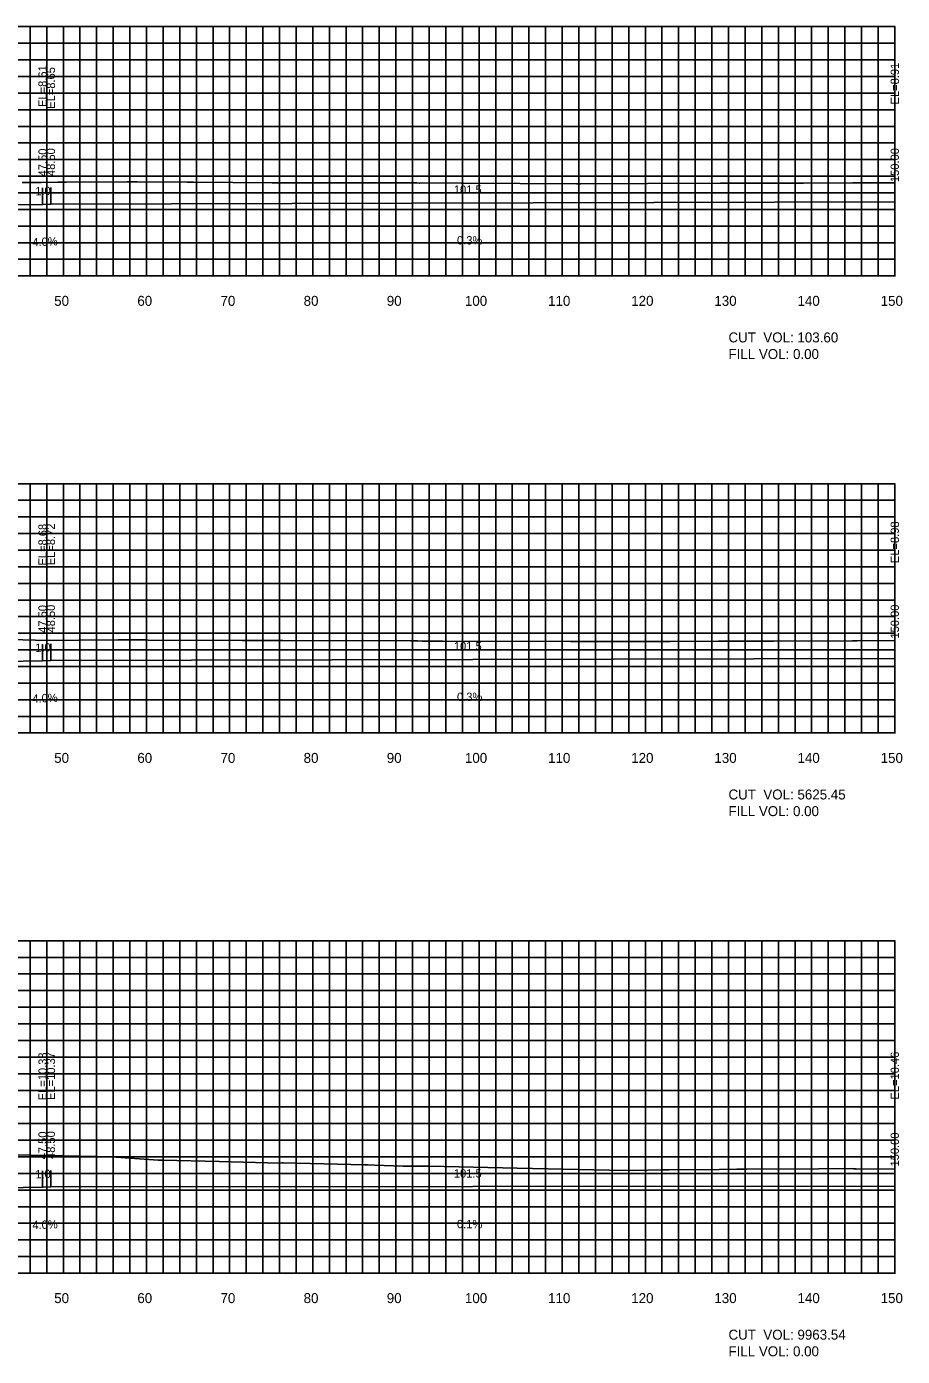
# Model space of a CAD drawing. Extents: x 1797789 to 1803805, y 249066 to 250293.
# Drawn here: x 1803356.6 to 1803461.9, y 250089.4 to 250249.4 of the extents above; entities that cross this region are included whole.
import ezdxf

# ---------------------------------------------------------------- set-up
doc = ezdxf.new("R2010")
doc.units = 0
for name, color, linetype in [('10', 7, 'Continuous'), ('3', 7, 'Continuous'), ('4', 7, 'Continuous'), ('60', 7, 'Continuous'), ('ANNO-TXT', 7, 'Continuous'), ('CL-CNST', 7, 'Continuous'), ('Level 62', 7, 'Continuous'), ('M-ROADS', 7, 'Continuous')]:
    doc.layers.add(name, color=color, linetype=linetype)

msp = doc.modelspace()

# ---------------------------------------------------------------- linework, layer by layer
for p, q in [((1803358.5, 250228.04), (1803358.5, 250230.04)), ((1803359.5, 250228.08), (1803359.5, 250230.08)), ((1803461, 250228.34), (1803461, 250230.34)), ((1803358.5, 250173.11), (1803358.5, 250175.11)), ((1803359.5, 250173.15), (1803359.5, 250175.15)), ((1803461, 250173.41), (1803461, 250175.41)), ((1803358.5, 250109.76), (1803358.5, 250111.76)), ((1803359.5, 250109.8), (1803359.5, 250111.8)), ((1803461, 250109.89), (1803461, 250111.89))]:
    msp.add_line(p, q)
at = {"layer": '60'}
for p, q in [((1803461, 250219.43), (1803461, 250249.43)), ((1803461.06, 250249.43), (1803461, 250249.43)), ((1803461.06, 250239.43), (1803461, 250239.43)), ((1803461.06, 250229.43), (1803461, 250229.43)), ((1803161, 250219.43), (1803461, 250219.43)), ((1803361, 250219.37), (1803361, 250219.43)), ((1803371, 250219.37), (1803371, 250219.43)), ((1803381, 250219.37), (1803381, 250219.43)), ((1803391, 250219.37), (1803391, 250219.43)), ((1803401, 250219.37), (1803401, 250219.43)), ((1803411, 250219.37), (1803411, 250219.43)), ((1803421, 250219.37), (1803421, 250219.43)), ((1803431, 250219.37), (1803431, 250219.43)), ((1803441, 250219.37), (1803441, 250219.43)), ((1803451, 250219.37), (1803451, 250219.43)), ((1803461, 250219.37), (1803461, 250219.43)), ((1803461.06, 250219.43), (1803461, 250219.43)), ((1803461, 250164.43), (1803461, 250194.43)), ((1803461.06, 250194.43), (1803461, 250194.43)), ((1803461.06, 250184.43), (1803461, 250184.43)), ((1803461.06, 250174.43), (1803461, 250174.43)), ((1803161, 250164.43), (1803461, 250164.43)), ((1803361, 250164.37), (1803361, 250164.43)), ((1803371, 250164.37), (1803371, 250164.43)), ((1803381, 250164.37), (1803381, 250164.43)), ((1803391, 250164.37), (1803391, 250164.43)), ((1803401, 250164.37), (1803401, 250164.43)), ((1803411, 250164.37), (1803411, 250164.43)), ((1803421, 250164.37), (1803421, 250164.43)), ((1803431, 250164.37), (1803431, 250164.43)), ((1803441, 250164.37), (1803441, 250164.43)), ((1803451, 250164.37), (1803451, 250164.43)), ((1803461, 250164.37), (1803461, 250164.43)), ((1803461.06, 250164.43), (1803461, 250164.43)), ((1803461, 250099.43), (1803461, 250139.43)), ((1803461.06, 250139.43), (1803461, 250139.43)), ((1803461.06, 250129.43), (1803461, 250129.43)), ((1803461.06, 250119.43), (1803461, 250119.43)), ((1803461.06, 250109.43), (1803461, 250109.43)), ((1803161, 250099.43), (1803461, 250099.43)), ((1803361, 250099.37), (1803361, 250099.43)), ((1803371, 250099.37), (1803371, 250099.43)), ((1803381, 250099.37), (1803381, 250099.43)), ((1803391, 250099.37), (1803391, 250099.43)), ((1803401, 250099.37), (1803401, 250099.43)), ((1803411, 250099.37), (1803411, 250099.43)), ((1803421, 250099.37), (1803421, 250099.43)), ((1803431, 250099.37), (1803431, 250099.43)), ((1803441, 250099.37), (1803441, 250099.43)), ((1803451, 250099.37), (1803451, 250099.43)), ((1803461, 250099.37), (1803461, 250099.43)), ((1803461.06, 250099.43), (1803461, 250099.43))]:
    msp.add_line(p, q, dxfattribs=at)
at = {"layer": 'CL-CNST'}
for points in [[(1803249.99, 250232.25), (1803262.5, 250228.08), (1803263.5, 250228.04), (1803270.5, 250227.93), (1803270.5, 250227.93), (1803270.83, 250227.93), (1803271, 250227.43), (1803273, 250227.59), (1803277, 250227.68), (1803311, 250228.43), (1803345, 250227.68), (1803349, 250227.59), (1803351, 250227.43), (1803351.17, 250227.93), (1803351.5, 250227.93), (1803351.5, 250227.93), (1803358.5, 250228.04), (1803359.5, 250228.08), (1803461, 250228.34)], [(1803249.62, 250177.45), (1803262.5, 250173.15), (1803263.5, 250173.11), (1803270.5, 250173.01), (1803270.5, 250173.01), (1803270.83, 250173.01), (1803271, 250172.51), (1803273, 250172.67), (1803277, 250172.76), (1803311, 250173.5), (1803345, 250172.76), (1803349, 250172.67), (1803351, 250172.51), (1803351.17, 250173.01), (1803351.5, 250173.01), (1803351.5, 250173.01), (1803358.5, 250173.11), (1803359.5, 250173.15), (1803461, 250173.41)], [(1803161, 250111.29), (1803262.5, 250109.8), (1803263.5, 250109.76), (1803270.5, 250109.65), (1803270.5, 250109.65), (1803270.83, 250109.65), (1803271, 250109.15), (1803273, 250109.31), (1803277, 250109.4), (1803311, 250110.15), (1803345, 250109.4), (1803349, 250109.31), (1803351, 250109.15), (1803351.17, 250109.65), (1803351.5, 250109.65), (1803351.5, 250109.65), (1803358.5, 250109.76), (1803359.5, 250109.8), (1803461, 250109.89)]]:
    msp.add_lwpolyline(points, dxfattribs=at)
at = {"layer": 'Level 62'}
for p, q in [((1803161, 250249.43), (1803461, 250249.43)), ((1803357, 250219.43), (1803357, 250249.43)), ((1803359, 250219.43), (1803359, 250249.43)), ((1803361, 250219.43), (1803361, 250249.43)), ((1803363, 250219.43), (1803363, 250249.43)), ((1803365, 250219.43), (1803365, 250249.43)), ((1803367, 250219.43), (1803367, 250249.43)), ((1803369, 250219.43), (1803369, 250249.43)), ((1803371, 250219.43), (1803371, 250249.43)), ((1803373, 250219.43), (1803373, 250249.43)), ((1803375, 250219.43), (1803375, 250249.43)), ((1803377, 250219.43), (1803377, 250249.43)), ((1803379, 250219.43), (1803379, 250249.43)), ((1803381, 250219.43), (1803381, 250249.43)), ((1803383, 250219.43), (1803383, 250249.43)), ((1803385, 250219.43), (1803385, 250249.43)), ((1803387, 250219.43), (1803387, 250249.43)), ((1803389, 250219.43), (1803389, 250249.43)), ((1803391, 250219.43), (1803391, 250249.43)), ((1803393, 250219.43), (1803393, 250249.43)), ((1803395, 250219.43), (1803395, 250249.43)), ((1803397, 250219.43), (1803397, 250249.43)), ((1803399, 250219.43), (1803399, 250249.43)), ((1803401, 250219.43), (1803401, 250249.43)), ((1803403, 250219.43), (1803403, 250249.43)), ((1803405, 250219.43), (1803405, 250249.43)), ((1803407, 250219.43), (1803407, 250249.43)), ((1803409, 250219.43), (1803409, 250249.43)), ((1803411, 250219.43), (1803411, 250249.43)), ((1803413, 250219.43), (1803413, 250249.43)), ((1803415, 250219.43), (1803415, 250249.43)), ((1803417, 250219.43), (1803417, 250249.43)), ((1803419, 250219.43), (1803419, 250249.43)), ((1803421, 250219.43), (1803421, 250249.43)), ((1803423, 250219.43), (1803423, 250249.43)), ((1803425, 250219.43), (1803425, 250249.43)), ((1803427, 250219.43), (1803427, 250249.43)), ((1803429, 250219.43), (1803429, 250249.43)), ((1803431, 250219.43), (1803431, 250249.43)), ((1803433, 250219.43), (1803433, 250249.43)), ((1803435, 250219.43), (1803435, 250249.43)), ((1803437, 250219.43), (1803437, 250249.43)), ((1803439, 250219.43), (1803439, 250249.43)), ((1803441, 250219.43), (1803441, 250249.43)), ((1803443, 250219.43), (1803443, 250249.43)), ((1803445, 250219.43), (1803445, 250249.43)), ((1803447, 250219.43), (1803447, 250249.43)), ((1803449, 250219.43), (1803449, 250249.43)), ((1803451, 250219.43), (1803451, 250249.43)), ((1803453, 250219.43), (1803453, 250249.43)), ((1803455, 250219.43), (1803455, 250249.43)), ((1803457, 250219.43), (1803457, 250249.43)), ((1803459, 250219.43), (1803459, 250249.43)), ((1803461, 250219.43), (1803461, 250249.43)), ((1803161, 250247.43), (1803461, 250247.43)), ((1803161, 250245.43), (1803461, 250245.43)), ((1803161, 250243.43), (1803461, 250243.43)), ((1803161, 250241.43), (1803461, 250241.43)), ((1803161, 250239.43), (1803461, 250239.43)), ((1803161, 250237.43), (1803461, 250237.43)), ((1803161, 250235.43), (1803461, 250235.43)), ((1803161, 250233.43), (1803461, 250233.43)), ((1803161, 250231.43), (1803461, 250231.43)), ((1803161, 250229.43), (1803461, 250229.43)), ((1803161, 250227.43), (1803461, 250227.43)), ((1803161, 250225.43), (1803461, 250225.43)), ((1803161, 250223.43), (1803461, 250223.43)), ((1803161, 250221.43), (1803461, 250221.43)), ((1803161, 250219.43), (1803461, 250219.43)), ((1803161, 250194.43), (1803461, 250194.43)), ((1803357, 250164.43), (1803357, 250194.43)), ((1803359, 250164.43), (1803359, 250194.43)), ((1803361, 250164.43), (1803361, 250194.43)), ((1803363, 250164.43), (1803363, 250194.43)), ((1803365, 250164.43), (1803365, 250194.43)), ((1803367, 250164.43), (1803367, 250194.43)), ((1803369, 250164.43), (1803369, 250194.43)), ((1803371, 250164.43), (1803371, 250194.43)), ((1803373, 250164.43), (1803373, 250194.43)), ((1803375, 250164.43), (1803375, 250194.43)), ((1803377, 250164.43), (1803377, 250194.43)), ((1803379, 250164.43), (1803379, 250194.43)), ((1803381, 250164.43), (1803381, 250194.43)), ((1803383, 250164.43), (1803383, 250194.43)), ((1803385, 250164.43), (1803385, 250194.43)), ((1803387, 250164.43), (1803387, 250194.43)), ((1803389, 250164.43), (1803389, 250194.43)), ((1803391, 250164.43), (1803391, 250194.43)), ((1803393, 250164.43), (1803393, 250194.43)), ((1803395, 250164.43), (1803395, 250194.43)), ((1803397, 250164.43), (1803397, 250194.43)), ((1803399, 250164.43), (1803399, 250194.43)), ((1803401, 250164.43), (1803401, 250194.43)), ((1803403, 250164.43), (1803403, 250194.43)), ((1803405, 250164.43), (1803405, 250194.43)), ((1803407, 250164.43), (1803407, 250194.43)), ((1803409, 250164.43), (1803409, 250194.43)), ((1803411, 250164.43), (1803411, 250194.43)), ((1803413, 250164.43), (1803413, 250194.43)), ((1803415, 250164.43), (1803415, 250194.43)), ((1803417, 250164.43), (1803417, 250194.43)), ((1803419, 250164.43), (1803419, 250194.43)), ((1803421, 250164.43), (1803421, 250194.43)), ((1803423, 250164.43), (1803423, 250194.43)), ((1803425, 250164.43), (1803425, 250194.43)), ((1803427, 250164.43), (1803427, 250194.43)), ((1803429, 250164.43), (1803429, 250194.43)), ((1803431, 250164.43), (1803431, 250194.43)), ((1803433, 250164.43), (1803433, 250194.43)), ((1803435, 250164.43), (1803435, 250194.43)), ((1803437, 250164.43), (1803437, 250194.43)), ((1803439, 250164.43), (1803439, 250194.43)), ((1803441, 250164.43), (1803441, 250194.43)), ((1803443, 250164.43), (1803443, 250194.43)), ((1803445, 250164.43), (1803445, 250194.43)), ((1803447, 250164.43), (1803447, 250194.43)), ((1803449, 250164.43), (1803449, 250194.43)), ((1803451, 250164.43), (1803451, 250194.43)), ((1803453, 250164.43), (1803453, 250194.43)), ((1803455, 250164.43), (1803455, 250194.43)), ((1803457, 250164.43), (1803457, 250194.43)), ((1803459, 250164.43), (1803459, 250194.43)), ((1803461, 250164.43), (1803461, 250194.43)), ((1803161, 250192.43), (1803461, 250192.43)), ((1803161, 250190.43), (1803461, 250190.43)), ((1803161, 250188.43), (1803461, 250188.43)), ((1803161, 250186.43), (1803461, 250186.43)), ((1803161, 250184.43), (1803461, 250184.43)), ((1803161, 250182.43), (1803461, 250182.43)), ((1803161, 250180.43), (1803461, 250180.43)), ((1803161, 250178.43), (1803461, 250178.43)), ((1803161, 250176.43), (1803461, 250176.43)), ((1803161, 250174.43), (1803461, 250174.43)), ((1803161, 250172.43), (1803461, 250172.43)), ((1803161, 250170.43), (1803461, 250170.43)), ((1803161, 250168.43), (1803461, 250168.43)), ((1803161, 250166.43), (1803461, 250166.43)), ((1803161, 250164.43), (1803461, 250164.43)), ((1803161, 250139.43), (1803461, 250139.43)), ((1803357, 250099.43), (1803357, 250139.43)), ((1803359, 250099.43), (1803359, 250139.43)), ((1803361, 250099.43), (1803361, 250139.43)), ((1803363, 250099.43), (1803363, 250139.43)), ((1803365, 250099.43), (1803365, 250139.43)), ((1803367, 250099.43), (1803367, 250139.43)), ((1803369, 250099.43), (1803369, 250139.43)), ((1803371, 250099.43), (1803371, 250139.43)), ((1803373, 250099.43), (1803373, 250139.43)), ((1803375, 250099.43), (1803375, 250139.43)), ((1803377, 250099.43), (1803377, 250139.43)), ((1803379, 250099.43), (1803379, 250139.43)), ((1803381, 250099.43), (1803381, 250139.43)), ((1803383, 250099.43), (1803383, 250139.43)), ((1803385, 250099.43), (1803385, 250139.43)), ((1803387, 250099.43), (1803387, 250139.43)), ((1803389, 250099.43), (1803389, 250139.43)), ((1803391, 250099.43), (1803391, 250139.43)), ((1803393, 250099.43), (1803393, 250139.43)), ((1803395, 250099.43), (1803395, 250139.43)), ((1803397, 250099.43), (1803397, 250139.43)), ((1803399, 250099.43), (1803399, 250139.43)), ((1803401, 250099.43), (1803401, 250139.43)), ((1803403, 250099.43), (1803403, 250139.43)), ((1803405, 250099.43), (1803405, 250139.43)), ((1803407, 250099.43), (1803407, 250139.43)), ((1803409, 250099.43), (1803409, 250139.43)), ((1803411, 250099.43), (1803411, 250139.43)), ((1803413, 250099.43), (1803413, 250139.43)), ((1803415, 250099.43), (1803415, 250139.43)), ((1803417, 250099.43), (1803417, 250139.43)), ((1803419, 250099.43), (1803419, 250139.43)), ((1803421, 250099.43), (1803421, 250139.43)), ((1803423, 250099.43), (1803423, 250139.43)), ((1803425, 250099.43), (1803425, 250139.43)), ((1803427, 250099.43), (1803427, 250139.43)), ((1803429, 250099.43), (1803429, 250139.43)), ((1803431, 250099.43), (1803431, 250139.43)), ((1803433, 250099.43), (1803433, 250139.43)), ((1803435, 250099.43), (1803435, 250139.43)), ((1803437, 250099.43), (1803437, 250139.43)), ((1803439, 250099.43), (1803439, 250139.43)), ((1803441, 250099.43), (1803441, 250139.43)), ((1803443, 250099.43), (1803443, 250139.43)), ((1803445, 250099.43), (1803445, 250139.43)), ((1803447, 250099.43), (1803447, 250139.43)), ((1803449, 250099.43), (1803449, 250139.43)), ((1803451, 250099.43), (1803451, 250139.43)), ((1803453, 250099.43), (1803453, 250139.43)), ((1803455, 250099.43), (1803455, 250139.43)), ((1803457, 250099.43), (1803457, 250139.43)), ((1803459, 250099.43), (1803459, 250139.43)), ((1803461, 250099.43), (1803461, 250139.43)), ((1803161, 250137.43), (1803461, 250137.43)), ((1803161, 250135.43), (1803461, 250135.43)), ((1803161, 250133.43), (1803461, 250133.43)), ((1803161, 250131.43), (1803461, 250131.43)), ((1803161, 250129.43), (1803461, 250129.43)), ((1803161, 250127.43), (1803461, 250127.43)), ((1803161, 250125.43), (1803461, 250125.43)), ((1803161, 250123.43), (1803461, 250123.43)), ((1803161, 250121.43), (1803461, 250121.43)), ((1803161, 250119.43), (1803461, 250119.43)), ((1803161, 250117.43), (1803461, 250117.43)), ((1803161, 250115.43), (1803461, 250115.43)), ((1803161, 250113.43), (1803461, 250113.43)), ((1803161, 250111.43), (1803461, 250111.43)), ((1803161, 250109.43), (1803461, 250109.43)), ((1803161, 250107.43), (1803461, 250107.43)), ((1803161, 250105.43), (1803461, 250105.43)), ((1803161, 250103.43), (1803461, 250103.43)), ((1803161, 250101.43), (1803461, 250101.43)), ((1803161, 250099.43), (1803461, 250099.43))]:
    msp.add_line(p, q, dxfattribs=at)
at = {"layer": 'M-ROADS'}
for points in [[(1803356.04, 250230.67), (1803358.32, 250230.69), (1803360.35, 250230.7), (1803361.35, 250230.71), (1803368.69, 250230.76), (1803369.38, 250230.76), (1803369.43, 250230.75), (1803369.89, 250230.75), (1803375.91, 250230.71), (1803376.65, 250230.7), (1803386.12, 250230.65), (1803386.16, 250230.65), (1803400.58, 250230.62), (1803400.68, 250230.62), (1803403.51, 250230.62), (1803403.81, 250230.61), (1803403.88, 250230.61), (1803404.16, 250230.62), (1803408.88, 250230.58), (1803409.14, 250230.59), (1803422.7, 250230.53), (1803422.9, 250230.53), (1803423.07, 250230.52), (1803423.26, 250230.53), (1803431.25, 250230.55), (1803440.02, 250230.58), (1803450.04, 250230.61), (1803455.94, 250230.63), (1803456.09, 250230.63), (1803456.35, 250230.63), (1803456.46, 250230.63), (1803461, 250230.64)], [(1803353, 250175.73), (1803357.64, 250175.59), (1803358.09, 250175.58), (1803367.6, 250175.64), (1803370.69, 250175.63), (1803370.92, 250175.63), (1803371.19, 250175.62), (1803382.5, 250175.55), (1803382.71, 250175.56), (1803383.43, 250175.56), (1803385.36, 250175.57), (1803386.77, 250175.56), (1803387.34, 250175.56), (1803387.41, 250175.56), (1803402.77, 250175.51), (1803403.14, 250175.51), (1803403.57, 250175.51), (1803403.59, 250175.51), (1803404.17, 250175.5), (1803406.64, 250175.49), (1803422.04, 250175.43), (1803422.33, 250175.42), (1803422.4, 250175.42), (1803422.68, 250175.43), (1803434, 250175.46), (1803439.78, 250175.48), (1803446.42, 250175.5), (1803455.9, 250175.54), (1803456.14, 250175.54), (1803456.31, 250175.53), (1803456.47, 250175.54), (1803461, 250175.55)], [(1803355.06, 250113.69), (1803366.89, 250113.44), (1803367.18, 250113.42), (1803367.36, 250113.4), (1803372.41, 250113.02), (1803372.58, 250113.02), (1803372.95, 250113.02), (1803379.76, 250112.87), (1803387.01, 250112.68), (1803387.28, 250112.69), (1803387.44, 250112.69), (1803397.23, 250112.47), (1803397.62, 250112.45), (1803398.41, 250112.42), (1803401.87, 250112.32), (1803403.41, 250112.29), (1803403.87, 250112.3), (1803405.03, 250112.3), (1803415.58, 250112.05), (1803426.63, 250111.81), (1803429.58, 250111.8), (1803432.98, 250111.88), (1803433.83, 250111.88), (1803439.87, 250111.91), (1803441.99, 250111.94), (1803442.14, 250111.95), (1803442.91, 250111.96), (1803443.18, 250111.96), (1803451.86, 250111.99), (1803455.88, 250112.01), (1803456.05, 250112), (1803456.37, 250111.99), (1803461, 250111.96)]]:
    msp.add_lwpolyline(points, dxfattribs=at)

# ---------------------------------------------------------------- texts
at = {"layer": '10'}
for s, p in [('50', (1803359.9, 250215.83)), ('60', (1803369.9, 250215.83)), ('70', (1803379.9, 250215.83)), ('80', (1803389.9, 250215.83)), ('90', (1803399.9, 250215.83)), ('100', (1803409.3, 250215.83)), ('110', (1803419.3, 250215.83)), ('120', (1803429.3, 250215.83)), ('130', (1803439.3, 250215.83)), ('140', (1803449.3, 250215.83)), ('150', (1803459.3, 250215.83)), ('50', (1803359.9, 250160.83)), ('60', (1803369.9, 250160.83)), ('70', (1803379.9, 250160.83)), ('80', (1803389.9, 250160.83)), ('90', (1803399.9, 250160.83)), ('100', (1803409.3, 250160.83)), ('110', (1803419.3, 250160.83)), ('120', (1803429.3, 250160.83)), ('130', (1803439.3, 250160.83)), ('140', (1803449.3, 250160.83)), ('150', (1803459.3, 250160.83)), ('50', (1803359.9, 250095.83)), ('60', (1803369.9, 250095.83)), ('70', (1803379.9, 250095.83)), ('80', (1803389.9, 250095.83)), ('90', (1803399.9, 250095.83)), ('100', (1803409.3, 250095.83)), ('110', (1803419.3, 250095.83)), ('120', (1803429.3, 250095.83)), ('130', (1803439.3, 250095.83)), ('140', (1803449.3, 250095.83)), ('150', (1803459.3, 250095.83))]:
    msp.add_text(s, height=1.2, dxfattribs=at).set_placement(p)
at = {"layer": '3'}
for s, p in [('EL=8.61', (1803359, 250239.76)), ('EL=8.65', (1803360, 250239.54)), ('EL=8.91', (1803461.5, 250240.06)), ('47.50', (1803359, 250231.41)), ('48.50', (1803360, 250231.45)), ('150.00', (1803461.5, 250230.72)), ('EL=8.98', (1803461.5, 250184.87)), ('EL=8.68', (1803359, 250184.58)), ('EL=8.72', (1803360, 250184.62)), ('47.50', (1803359, 250176.48)), ('48.50', (1803360, 250176.52)), ('150.00', (1803461.5, 250175.79)), ('EL=10.33', (1803359, 250120.23)), ('EL=10.37', (1803360, 250120.27)), ('EL=10.46', (1803461.5, 250120.32)), ('47.50', (1803359, 250113.13)), ('48.50', (1803360, 250113.17)), ('150.00', (1803461.5, 250112.27))]:
    msp.add_text(s, height=1, rotation=90, dxfattribs=at).set_placement(p)
at = {"layer": '4'}
for s, rotation, p in [('1.0', 2.2906, (1803357.64, 250229.11)), ('101.5', 0.1492, (1803407.97, 250229.31)), ('4.0%', 2.2906, (1803357.29, 250222.99)), ('0.3%', 0.1492, (1803408.35, 250223.21)), ('1.0', 2.2906, (1803357.64, 250174.18)), ('101.5', 0.1441, (1803407.97, 250174.38)), ('4.0%', 2.2906, (1803357.29, 250168.06)), ('0.3%', 0.1441, (1803408.35, 250168.28)), ('1.0', 2.2906, (1803357.64, 250110.82)), ('101.5', 0.0545, (1803407.97, 250110.94)), ('4.0%', 2.2906, (1803357.29, 250104.71)), ('0.1%', 0.0545, (1803408.34, 250104.84))]:
    msp.add_text(s, height=1, rotation=rotation, dxfattribs=at).set_placement(p)
at = {"layer": 'ANNO-TXT'}
for s, p in [('CUT  VOL: 103.60', (1803441, 250211.43)), ('FILL VOL: 0.00', (1803441, 250209.43)), ('CUT  VOL: 5625.45', (1803441, 250156.43)), ('FILL VOL: 0.00', (1803441, 250154.43)), ('CUT  VOL: 9963.54', (1803441, 250091.43)), ('FILL VOL: 0.00', (1803441, 250089.43))]:
    msp.add_text(s, height=1.2, dxfattribs=at).set_placement(p)

doc.saveas('drawing.dxf')
